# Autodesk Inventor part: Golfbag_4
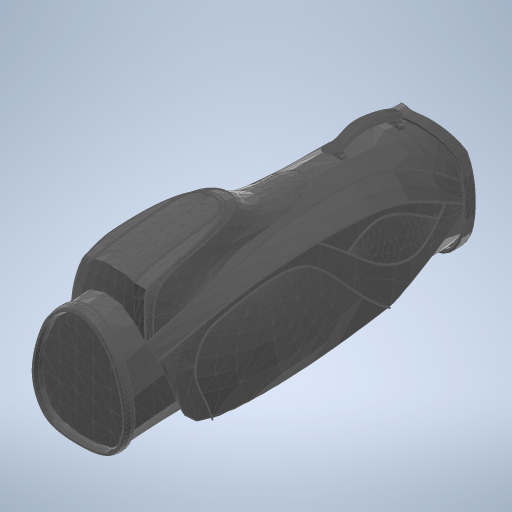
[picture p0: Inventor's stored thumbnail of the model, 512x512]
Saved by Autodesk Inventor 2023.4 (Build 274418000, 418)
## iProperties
Created: 2025-03
Part Number: Golfbag_4
Material: Générique
Document SubType Name: Modeling
Designer: bruno
Density: 1 g/cm^3
Appearance: Par défaut
Author: bruno
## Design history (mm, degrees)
node "Golfbag__4"
  node "FonctionMaillage1"
